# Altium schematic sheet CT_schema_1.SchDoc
size 514 x 462 mm
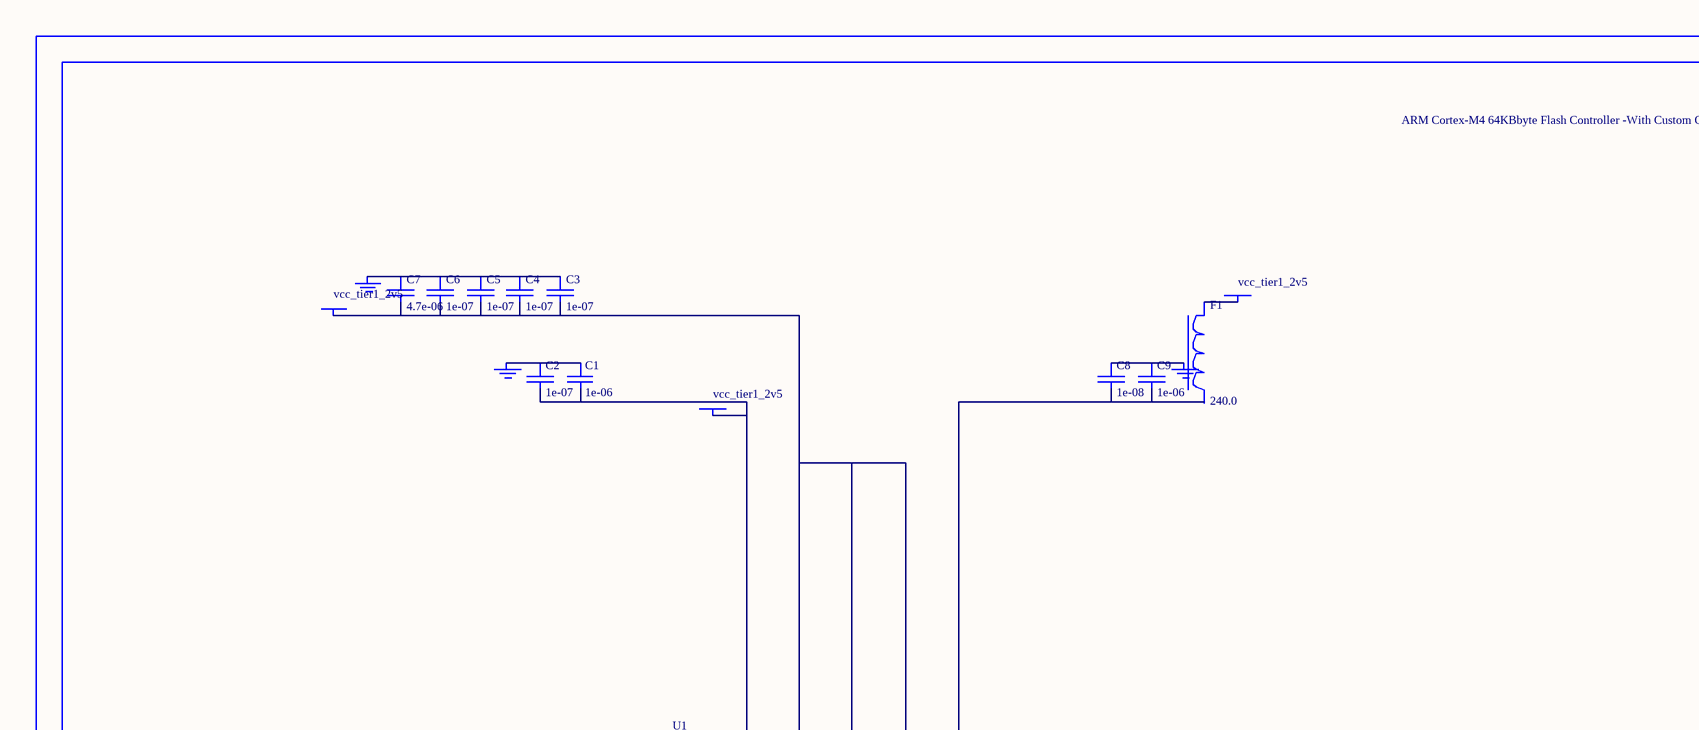
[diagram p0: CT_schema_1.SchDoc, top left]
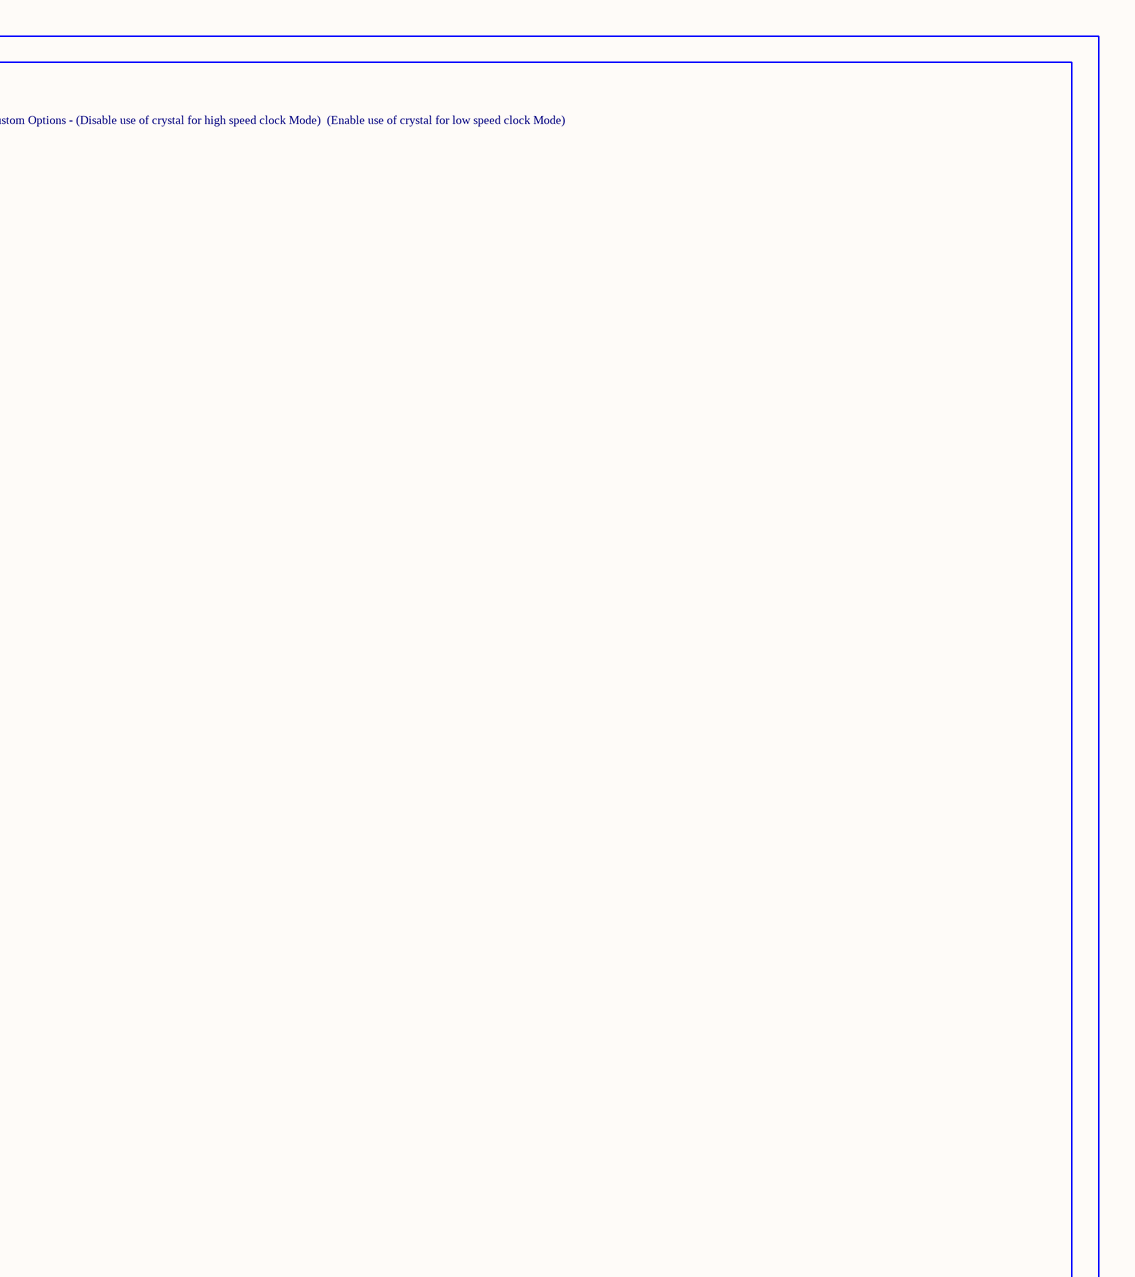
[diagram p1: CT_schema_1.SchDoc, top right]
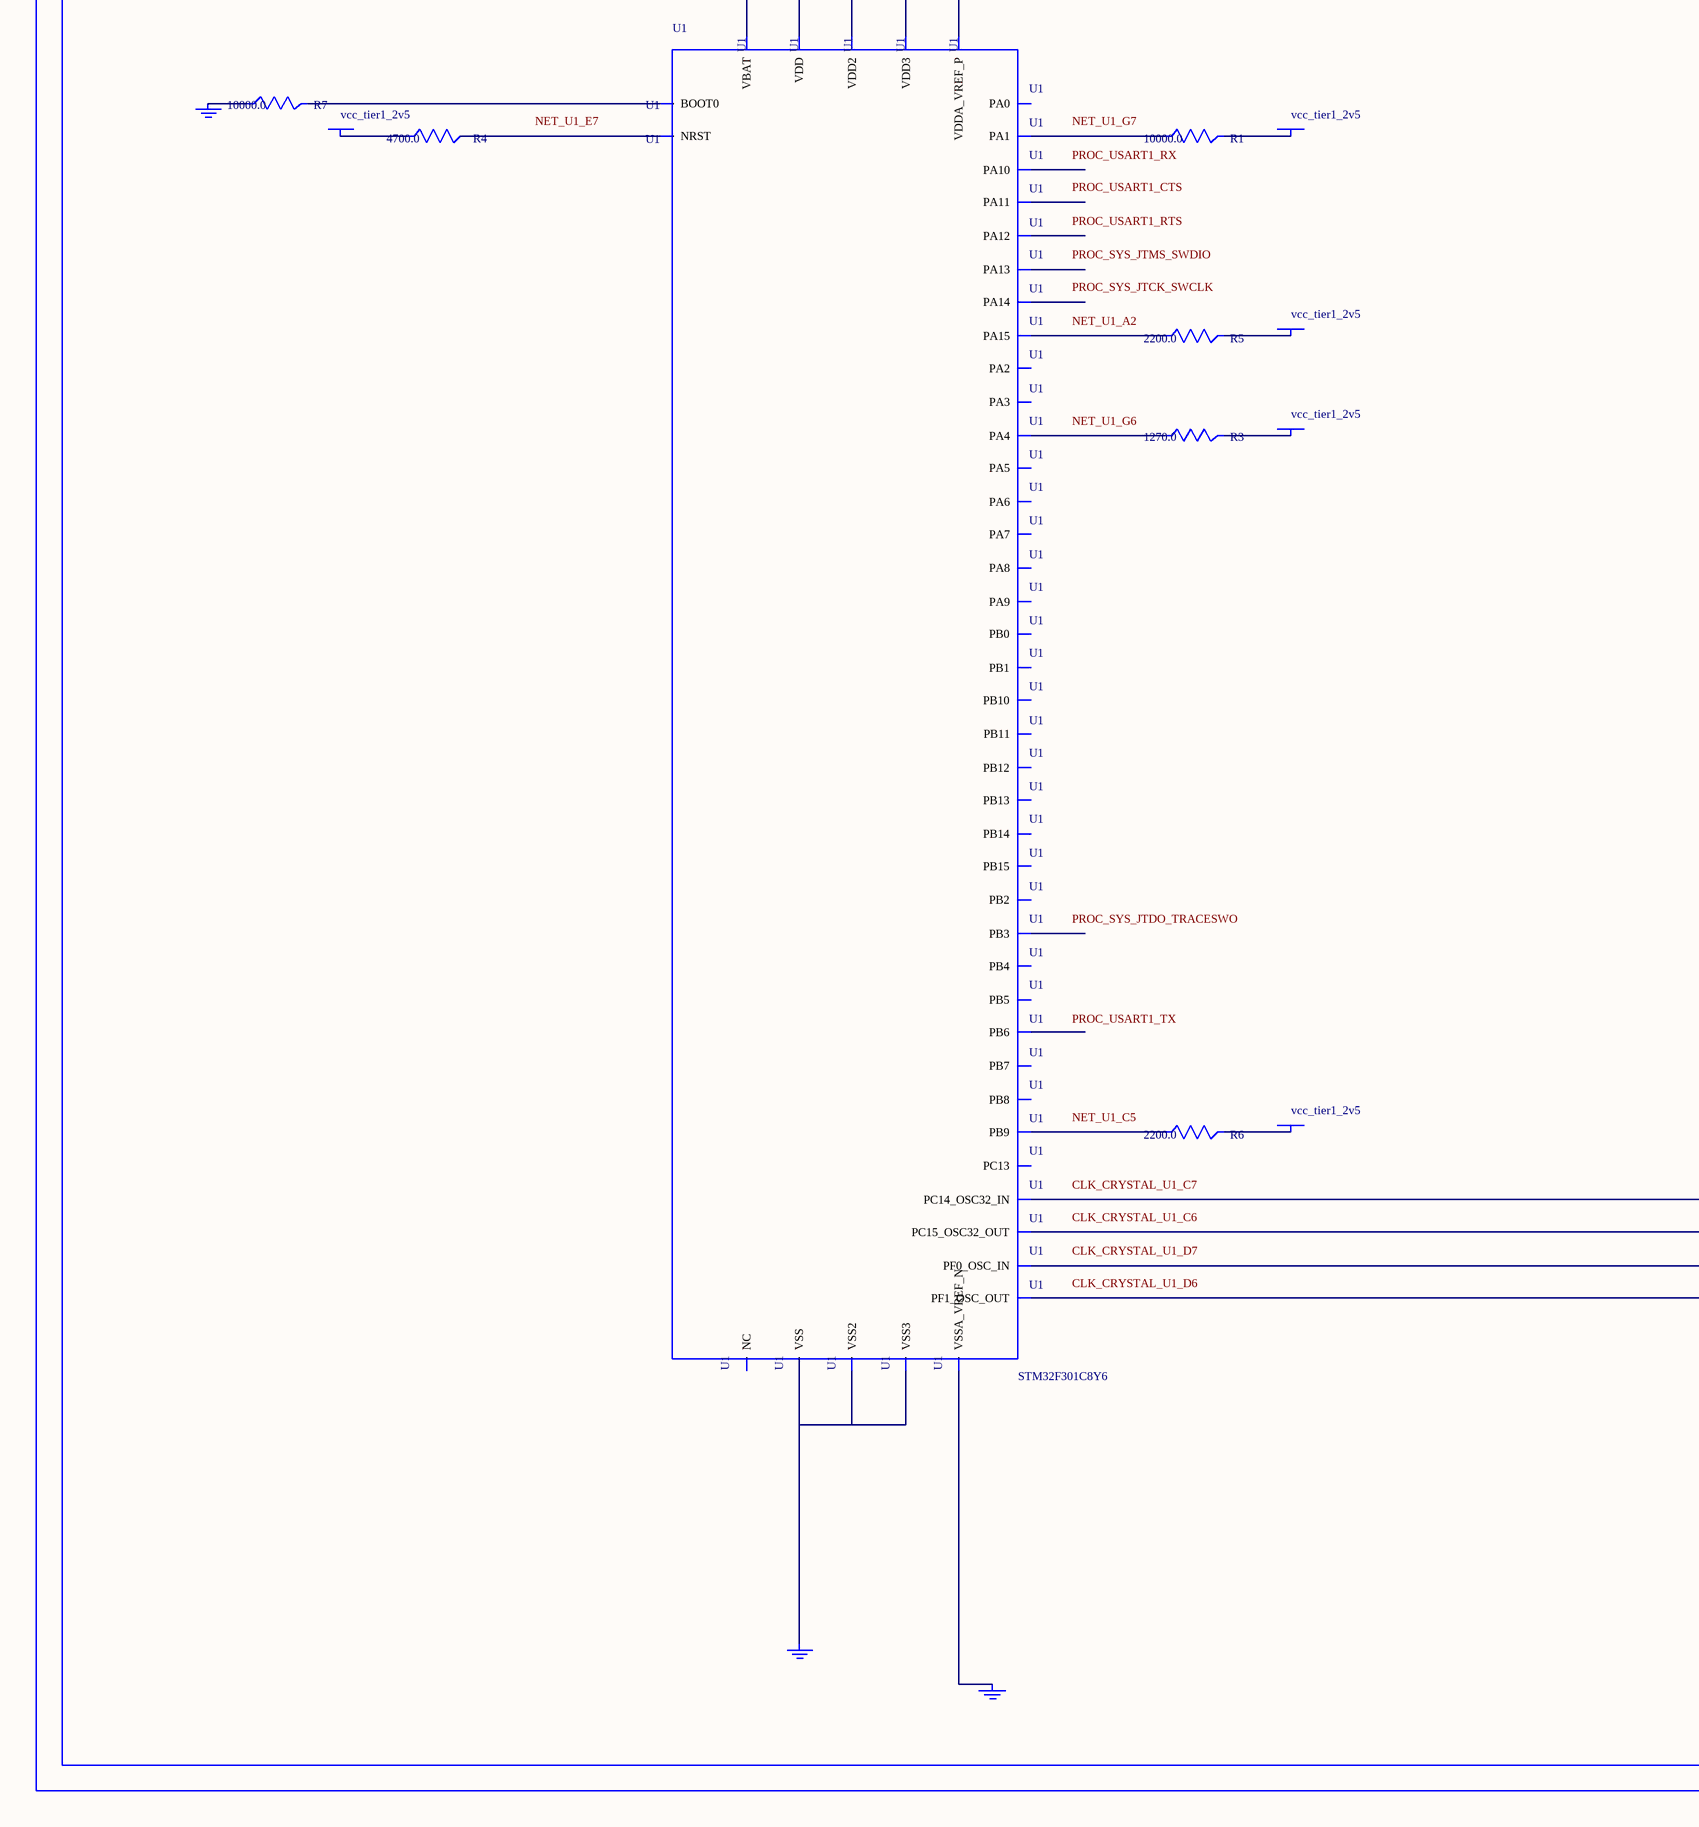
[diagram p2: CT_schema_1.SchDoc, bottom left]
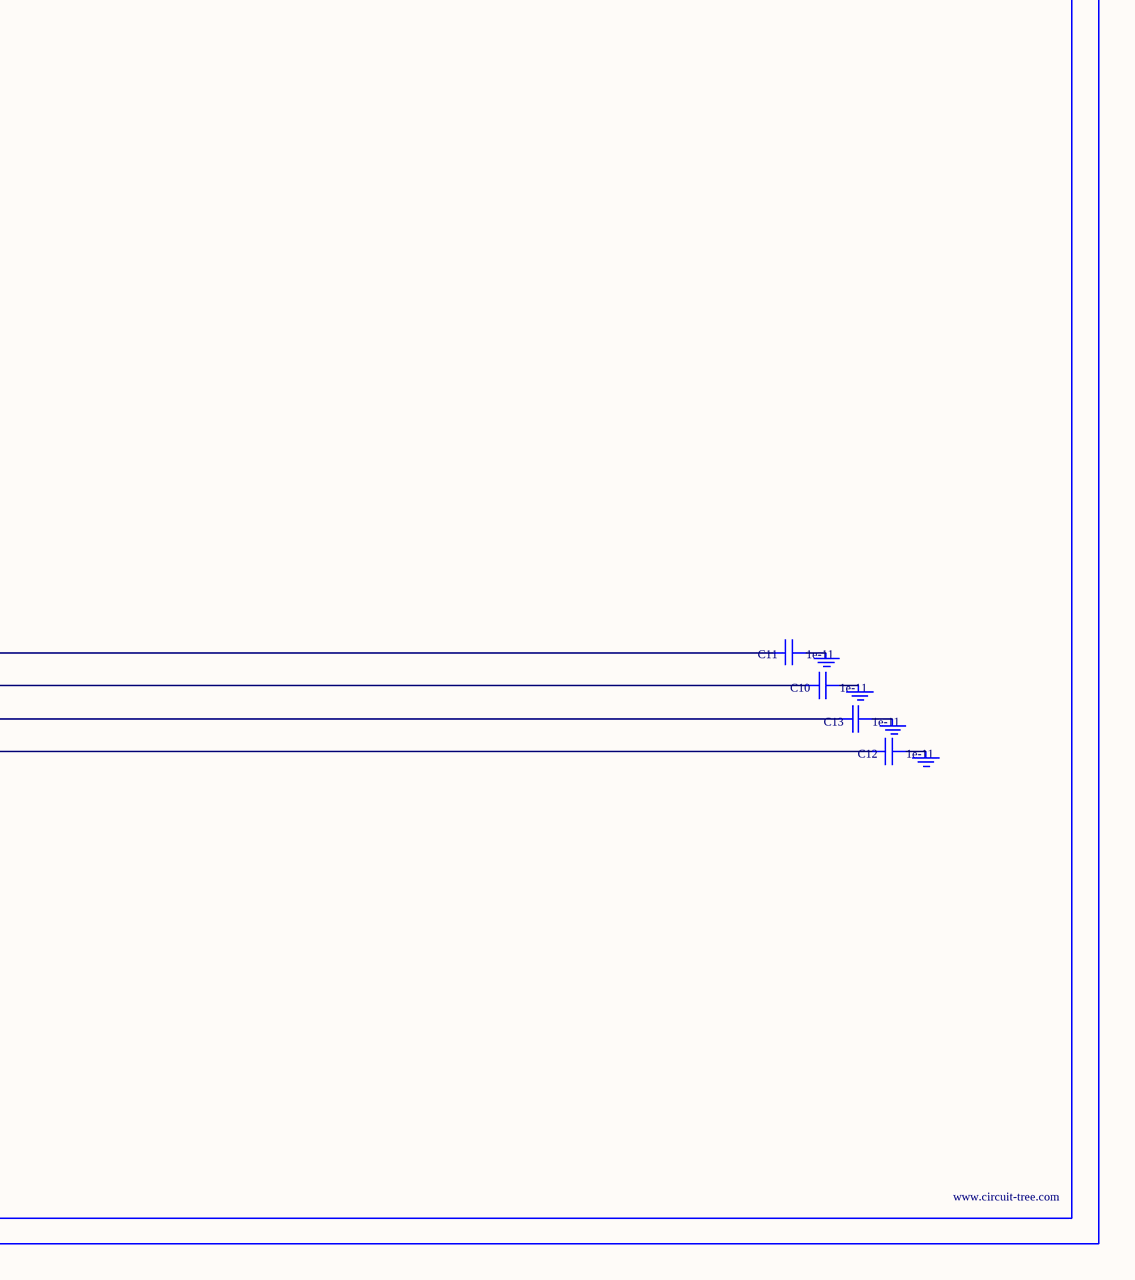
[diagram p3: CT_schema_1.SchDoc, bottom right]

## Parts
BORDER0  (no value)
C1  1e-06  [C0603]
C2  1e-07  [C0603]
C3  1e-07  [C0603]
C4  1e-07  [C0603]
C5  1e-07  [C0603]
C6  1e-07  [C0603]
C7  4.7e-06  [C0603]
C8  1e-08  [C0603]
C9  1e-06  [C0603]
C10  1e-11  [C0402]
C11  1e-11  [C0402]
C12  1e-11  [C0402]
C13  1e-11  [C0402]
F1  240.0  [L0603]
GND_INSTANCE_0_0  (no value)
GND_INSTANCE_0_1  (no value)
GND_INSTANCE_0_2  (no value)
GND_INSTANCE_0_3  (no value)
GND_INSTANCE_0_4  (no value)
GND_INSTANCE_0_5  (no value)
GND_INSTANCE_0_6  (no value)
GND_INSTANCE_0_7  (no value)
GND_INSTANCE_0_8  (no value)
GND_INSTANCE_0_9  (no value)
POWER_INSTANCE_0_0  vcc_tier1_2v5
POWER_INSTANCE_0_1  vcc_tier1_2v5
POWER_INSTANCE_0_2  vcc_tier1_2v5
POWER_INSTANCE_0_3  vcc_tier1_2v5
POWER_INSTANCE_0_4  vcc_tier1_2v5
POWER_INSTANCE_0_5  vcc_tier1_2v5
POWER_INSTANCE_0_6  vcc_tier1_2v5
POWER_INSTANCE_0_7  vcc_tier1_2v5
R1  10000.0  [R0603]
R3  1270.0  [R0603]
R4  4700.0  [R0603]
R5  2200.0  [R0603]
R6  2200.0  [R0603]
R7  10000.0  [R0603]
U1  STM32F301C8Y6  [WLCSP49]

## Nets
NetC1_1: C1.1 C2.1 GND_INSTANCE_0_0.0(GND)
NetC1_2: C1.2 C2.2 POWER_INSTANCE_0_0.0(PWR) U1.B6(VBAT)
NetC3_1: C3.1 C4.1 C5.1 C6.1 C7.1 GND_INSTANCE_0_2.0(GND)
NetC3_2: C3.2 C4.2 C5.2 C6.2 C7.2 POWER_INSTANCE_0_2.0(PWR) U1.B2(VDD) U1.B7(VDD2) U1.F2(VDD3)
NetC8_1: C8.1 C9.1 GND_INSTANCE_0_1.0(GND)
NetC8_2: C8.2 C9.2 U1.A6(VDDA_VREF_P)
NetC10_1: C10.1 GND_INSTANCE_0_4.0(GND)
NetC10_2: C10.2 U1.C6(PC15_OSC32_OUT)
NetC11_1: C11.1 GND_INSTANCE_0_5.0(GND)
NetC11_2: C11.2 U1.C7(PC14_OSC32_IN)
NetC12_1: C12.1 GND_INSTANCE_0_6.0(GND)
NetC12_2: C12.2 U1.D6(PF1_OSC_OUT)
NetC13_1: C13.1 GND_INSTANCE_0_7.0(GND)
NetC13_2: C13.2 U1.D7(PF0_OSC_IN)
NetF1_1: F1.1 POWER_INSTANCE_0_1.0(PWR)
NetGND_INSTANCE_0_3_0: GND_INSTANCE_0_3.0(GND) R7.1
NetGND_INSTANCE_0_8_0: GND_INSTANCE_0_8.0(GND) U1.E6(VSSA_VREF_N)
NetGND_INSTANCE_0_9_0: GND_INSTANCE_0_9.0(GND) U1.B1(VSS) U1.D3(VSS2) U1.F7(VSS3)
NetPOWER_INSTANCE_0_3_0: POWER_INSTANCE_0_3.0(PWR) R4.1
NetPOWER_INSTANCE_0_4_0: POWER_INSTANCE_0_4.0(PWR) R1.2
NetPOWER_INSTANCE_0_5_0: POWER_INSTANCE_0_5.0(PWR) R5.2
NetPOWER_INSTANCE_0_6_0: POWER_INSTANCE_0_6.0(PWR) R3.2
NetPOWER_INSTANCE_0_7_0: POWER_INSTANCE_0_7.0(PWR) R6.2
NetR1_1: R1.1 U1.G7(PA1)
NetR3_1: R3.1 U1.G6(PA4)
NetR4_2: R4.2 U1.E7(NRST)
NetR5_1: R5.1 U1.A2(PA15)
NetR6_1: R6.1 U1.C5(PB9)
NetR7_2: R7.2 U1.A5(BOOT0)

Not connected (* = marked no-connect by the designer): F1 2; U1 A1(PA14) A3(PB3) A4(PB4) A7(NC) B3(PA13) B4(PB5) B5(PB8) C1(PA11) C2(PA10) C3(PA12) C4(PB6) D1(PA8) D2(PA9) D4(PB7) D5(PC13) E1(PB15) E2(PB12) E3(PB10) E4(PA3) E5(PA2) F1(PB14) F3(PA7) F4(PA6) F5(PA5) F6(PA0) G1(PB13) G2(PB11) G3(PB2) G4(PB1) G5(PB0)

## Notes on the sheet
- Labels drawn without touching a wire or pin: CLK_CRYSTAL_U1_C6, CLK_CRYSTAL_U1_C7, CLK_CRYSTAL_U1_D6, CLK_CRYSTAL_U1_D7, NET_U1_A2, NET_U1_C5, NET_U1_E7, NET_U1_G6, NET_U1_G7, PROC_SYS_JTCK_SWCLK, PROC_SYS_JTDO_TRACESWO, PROC_SYS_JTMS_SWDIO, PROC_USART1_CTS, PROC_USART1_RTS, PROC_USART1_RX, PROC_USART1_TX

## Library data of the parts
BORDER0 = BORDER_PAGE0
C1 C9 = C0603C105K3RACTU
C2-C6 = 06035C104K4Z2A
C7 = GRM188R6YA475KE15D
C8 = 06035C103K4Z2A
C10-C13 = C0402C100K3GACTU
F1 = Z0603C241ASMST
GND_INSTANCE_0_0-GND_INSTANCE_0_9 = GND
POWER_INSTANCE_0_0-POWER_INSTANCE_0_7 = PWR
R1 R7 = RC0603JR-0710KL
R3 = RC0603FR-071K27L
R4 = RC0603JR-074K7L
R5 R6 = RC0603JR-072K2L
